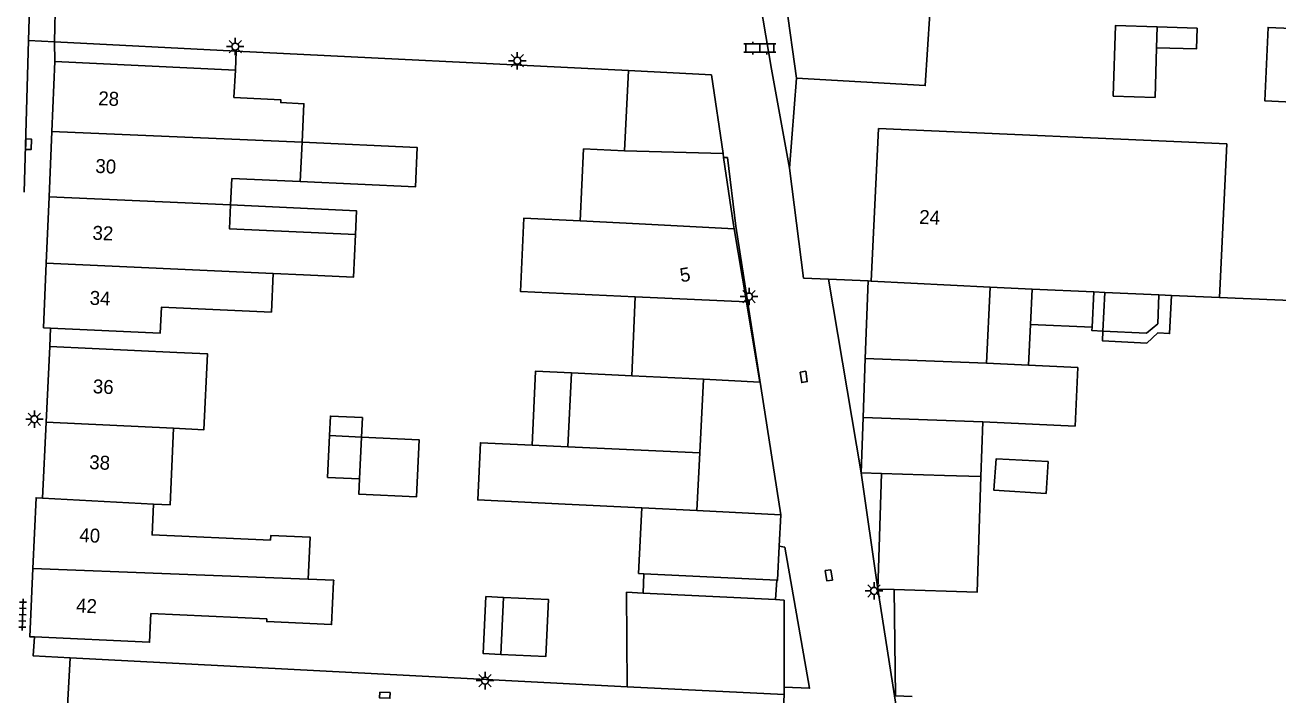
# Model space of a CAD drawing. Extents: x 132998 to 136004, y 396998 to 398512.
# Drawn here: x 133159.2 to 133249, y 397894.1 to 397942.1 of the extents above; entities that cross this region are included whole.
import ezdxf

# ---------------------------------------------------------------- set-up
doc = ezdxf.new("R2010")
doc.units = 0
for name, color, linetype in [('gg-afsc-erfafscheiding', 7, 'Continuous'), ('gg-afsc-hekwerk', 7, 'Continuous'), ('gg-afsc-muur', 7, 'Continuous'), ('gg-anno-huisnummerreeks BGT', 7, 'Continuous'), ('gg-bbg-bijgebouw', 7, 'Continuous'), ('gg-bbg-gedigitaliseerde bebouwing', 7, 'Continuous'), ('gg-bbg-gedigitaliseerde bijgebouw', 7, 'Continuous'), ('gg-bbg-hoofdgebouw', 7, 'Continuous'), ('gg-bbg-luifel en loopbrug', 7, 'Continuous'), ('gg-bbg-tussenscheiding', 7, 'Continuous'), ('gg-knt-verharding', 7, 'Continuous'), ('gt-grn-weggrens', 7, 'Continuous'), ('gt-symb-klinker verharding', 7, 'Continuous'), ('gt-symb-kolk', 7, 'Continuous'), ('gt-symb-kolk center center', 7, 'Continuous'), ('gt-symb-lichtmast', 7, 'Continuous'), ('gt-symb-tegel verharding', 7, 'Continuous')]:
    doc.layers.add(name, color=color, linetype=linetype)

# ---------------------------------------------------------------- blocks, each defined once
blk = doc.blocks.new('gt0-KL1')
at = {"layer": 'gt-symb-klinker verharding'}
for p, q in [((-1.15, 0.3), (1.15, 0.3)), ((-1, -0.3), (-1, 0.3)), ((-0.5, 0.3), (-0.5, 0.45)), ((0, -0.3), (0, 0.3)), ((0.5, 0.3), (0.5, 0.45)), ((1, -0.3), (1, 0.3)), ((-1.15, -0.3), (1.15, -0.3)), ((-0.5, -0.45), (-0.5, -0.3)), ((0.5, -0.45), (0.5, -0.3))]:
    blk.add_line(p, q, dxfattribs=at)
blk = doc.blocks.new('gt0-LMAST')
at = {"layer": 'gt-symb-lichtmast'}
for p, q in [((-0.182, 0.173), (-0.447, 0.438)), ((-0.005, 0.246), (-0.005, 0.621)), ((0.172, 0.173), (0.437, 0.438)), ((-0.255, -0.004), (-0.63, -0.004)), ((-0.182, -0.181), (-0.447, -0.446)), ((-0.005, -0.254), (-0.005, -0.629)), ((0.437, -0.446), (0.172, -0.181)), ((0.245, -0.004), (0.62, -0.004))]:
    blk.add_line(p, q, dxfattribs=at)
blk.add_circle((-0.005, -0.004), 0.25, dxfattribs=at)
blk = doc.blocks.new('gt0-KOLK')
at = {"layer": 'gt-symb-kolk'}
blk.add_lwpolyline([(0, 0), (0.375, 0), (0.375, 0.4), (-0.375, 0.4), (-0.375, 0), (0, 0)], dxfattribs=at)
blk = doc.blocks.new('gt0-KOLKCC')
at = {"layer": 'gt-symb-kolk center center'}
blk.add_lwpolyline([(-0.375, 0.2), (0.375, 0.2), (0.375, -0.2), (-0.375, -0.2)], close=True, dxfattribs=at)
blk = doc.blocks.new('gt0-TEG1')
at = {"layer": 'gt-symb-tegel verharding'}
for p, q in [((-1.125, 0), (1.125, 0)), ((-0.9, -0.25), (-0.9, 0.25)), ((-0.45, -0.25), (-0.45, 0.25)), ((0, -0.25), (0, 0.25)), ((0.45, -0.25), (0.45, 0.25)), ((0.9, -0.25), (0.9, 0.25))]:
    blk.add_line(p, q, dxfattribs=at)

msp = doc.modelspace()

# ---------------------------------------------------------------- linework, layer by layer
at = {"layer": 'gg-afsc-erfafscheiding'}
for p, q in [((133216.799, 397923.882), (133219.63, 397923.76)), ((133213.657, 397904.69), (133213.264, 397904.749)), ((133202.36, 397894.68), (133162.411, 397896.761))]:
    msp.add_line(p, q, dxfattribs=at)
for points in [[(133214.007, 397931.848), (133215.003, 397923.96), (133216.799, 397923.882)], [(133221.51, 397901.643), (133221.596, 397894.022), (133222.795, 397893.973)], [(133162.411, 397896.761), (133159.75, 397896.9), (133159.851, 397898.244)]]:
    msp.add_lwpolyline(points, dxfattribs=at)
at = {"layer": 'gg-afsc-hekwerk'}
msp.add_line((133214.5, 397938.29), (133214.007, 397931.848), dxfattribs=at)
at = {"layer": 'gg-afsc-muur'}
for p, q in [((133174.26, 397938.86), (133174.325, 397940.237)), ((133174.325, 397940.237), (133202.44, 397938.83)), ((133244.82, 397922.57), (133255.245, 397922.154))]:
    msp.add_line(p, q, dxfattribs=at)
at = {"layer": 'gg-bbg-bijgebouw'}
for p, q in [((133214.5, 397938.29), (133213.751, 397943.59)), ((133208.4, 397938.54), (133202.44, 397938.83)), ((133208.4, 397938.54), (133209.228, 397932.893)), ((133209.228, 397932.893), (133209.27, 397932.61)), ((133209.978, 397927.785), (133209.27, 397932.61)), ((133209.978, 397927.785), (133210.026, 397927.499)), ((133219.63, 397923.76), (133219.432, 397918.205)), ((133219.281, 397913.98), (133219.432, 397918.205)), ((133207.564, 397911.429), (133207.833, 397916.715)), ((133219.281, 397913.98), (133219.14, 397910.01)), ((133207.564, 397911.429), (133207.355, 397907.302)), ((133219.14, 397910.01), (133220.6, 397909.96)), ((133220.6, 397909.96), (133220.34, 397901.68)), ((133207.355, 397907.302), (133213.377, 397907.008)), ((133213.377, 397907.008), (133213.264, 397904.749)), ((133220.34, 397901.68), (133221.51, 397901.643)), ((133212.996, 397900.935), (133213.621, 397900.89)), ((133213.621, 397900.89), (133213.611, 397894.64)), ((133202.36, 397894.68), (133213.61, 397894.13)), ((133213.611, 397894.64), (133213.61, 397894.13))]:
    msp.add_line(p, q, dxfattribs=at)
for points in [[(133207.833, 397916.715), (133211.878, 397916.516), (133210.907, 397922.254)], [(133213.264, 397904.749), (133213.142, 397902.314), (133213.081, 397902.318)]]:
    msp.add_lwpolyline(points, dxfattribs=at)
at = {"layer": 'gg-bbg-gedigitaliseerde bebouwing'}
for p, q in [((133220.374, 397934.686), (133245.35, 397933.58)), ((133179.041, 397933.706), (133178.898, 397930.879)), ((133173.91, 397929.205), (133173.998, 397931.108)), ((133173.998, 397931.108), (133177.248, 397930.962)), ((133178.898, 397930.879), (133177.248, 397930.962)), ((133179.146, 397924.194), (133176.965, 397924.304)), ((133231.392, 397923.173), (133228.375, 397923.309)), ((133236.609, 397922.939), (133235.813, 397922.975)), ((133241.387, 397922.724), (133240.492, 397922.764)), ((133244.82, 397922.57), (133241.387, 397922.724)), ((133161.01, 397920.368), (133160.5, 397920.39)), ((133170.063, 397918.641), (133160.95, 397919.06)), ((133179.49, 397902.38), (133181.311, 397902.309))]:
    msp.add_line(p, q, dxfattribs=at)
for points in [[(133182.863, 397927.082), (133173.831, 397927.498), (133173.91, 397929.205)], [(133202.918, 397922.623), (133194.708, 397923.002), (133194.951, 397928.268), (133198.988, 397928.061)], [(133179.146, 397924.194), (133182.722, 397924.029), (133182.863, 397927.082)], [(133161.01, 397920.368), (133168.877, 397920.021), (133168.961, 397921.876), (133176.84, 397921.522), (133176.965, 397924.304)], [(133170.063, 397918.641), (133172.261, 397918.538), (133172.005, 397913.098), (133169.82, 397913.201)], [(133168.381, 397907.765), (133169.575, 397907.712), (133169.82, 397913.201)], [(133176.791, 397905.184), (133168.283, 397905.563), (133168.381, 397907.765)], [(133176.791, 397905.184), (133176.806, 397905.521), (133179.626, 397905.395), (133179.49, 397902.38)]]:
    msp.add_lwpolyline(points, dxfattribs=at)
at = {"layer": 'gg-bbg-gedigitaliseerde bijgebouw'}
for p, q in [((133240.367, 397941.963), (133240.32, 397940.475)), ((133202.164, 397933.083), (133202.44, 397938.83)), ((133228.113, 397917.859), (133228.375, 397923.309)), ((133231.27, 397920.639), (133231.392, 397923.173)), ((133235.691, 397920.44), (133235.813, 397922.975)), ((133236.609, 397922.939), (133236.476, 397920.16)), ((133202.689, 397916.963), (133202.918, 397922.623)), ((133231.27, 397920.639), (133235.691, 397920.44)), ((133231.129, 397917.714), (133228.113, 397917.859)), ((133198.102, 397911.873), (133198.357, 397917.171)), ((133198.357, 397917.171), (133202.689, 397916.963)), ((133227.713, 397909.736), (133227.853, 397913.674)), ((133183.305, 397912.568), (133183.171, 397909.571)), ((133195.538, 397911.993), (133198.102, 397911.873)), ((133203.399, 397907.497), (133197.904, 397907.762)), ((133213.081, 397902.318), (133203.561, 397902.777)), ((133212.996, 397900.935), (133203.494, 397901.393)), ((133193.293, 397896.989), (133193.478, 397901.078))]:
    msp.add_line(p, q, dxfattribs=at)
for points in [[(133213.751, 397943.59), (133224.06, 397942.934), (133223.732, 397937.765), (133214.5, 397938.29)], [(133237.209, 397937.012), (133237.369, 397942.058), (133240.367, 397941.963)], [(133240.32, 397940.475), (133240.207, 397936.917), (133237.209, 397937.012)], [(133202.164, 397933.083), (133199.236, 397933.22), (133198.988, 397928.061)], [(133236.476, 397920.16), (133239.602, 397920.02), (133240.399, 397920.688), (133240.492, 397922.764)], [(133227.853, 397913.674), (133234.47, 397913.356), (133234.671, 397917.544), (133231.129, 397917.714)], [(133183.305, 397912.568), (133183.367, 397913.966), (133181.07, 397914.075), (133181.007, 397912.676)], [(133183.171, 397909.571), (133180.873, 397909.679), (133181.007, 397912.676)], [(133197.904, 397907.762), (133191.639, 397908.064), (133191.836, 397912.167), (133195.538, 397911.993)], [(133232.397, 397908.535), (133228.656, 397908.763), (133228.81, 397911.01), (133232.537, 397910.819), (133232.397, 397908.535)], [(133227.713, 397909.736), (133227.453, 397901.452), (133221.51, 397901.643)], [(133203.561, 397902.777), (133203.17, 397902.796), (133203.399, 397907.497)], [(133203.494, 397901.393), (133202.313, 397901.45), (133202.36, 397894.68)], [(133193.478, 397901.078), (133196.703, 397900.932), (133196.519, 397896.843), (133193.293, 397896.989)]]:
    msp.add_lwpolyline(points, dxfattribs=at)
at = {"layer": 'gg-bbg-hoofdgebouw'}
for p, q in [((133161.32, 397939.48), (133161.105, 397934.476)), ((133174.26, 397938.86), (133161.32, 397939.48)), ((133220.374, 397934.686), (133219.856, 397923.748)), ((133161.105, 397934.476), (133160.903, 397929.777)), ((133244.82, 397922.57), (133245.35, 397933.58)), ((133160.903, 397929.777), (133160.7, 397925.035)), ((133210.026, 397927.499), (133210.907, 397922.254)), ((133160.7, 397925.035), (133160.5, 397920.39)), ((133219.856, 397923.748), (133219.63, 397923.76)), ((133160.95, 397919.06), (133160.695, 397913.63)), ((133160.695, 397913.63), (133160.44, 397908.2)), ((133181.305, 397902.187), (133181.311, 397902.309))]:
    msp.add_line(p, q, dxfattribs=at)
for points in [[(133174.26, 397938.86), (133174.16, 397936.91), (133177.52, 397936.74), (133177.51, 397936.54), (133179.17, 397936.46), (133179.041, 397933.706)], [(133160.44, 397908.2), (133159.97, 397908.22), (133159.741, 397903.15)], [(133159.741, 397903.15), (133159.52, 397898.26), (133159.851, 397898.244)], [(133159.851, 397898.244), (133168.111, 397897.872), (133168.204, 397899.92), (133176.515, 397899.543), (133176.506, 397899.353), (133181.161, 397899.133), (133181.305, 397902.187)]]:
    msp.add_lwpolyline(points, dxfattribs=at)
at = {"layer": 'gg-bbg-luifel en loopbrug'}
for p, q in [((133231.129, 397917.714), (133231.27, 397920.639)), ((133203.494, 397901.393), (133203.561, 397902.777)), ((133212.996, 397900.935), (133213.081, 397902.318))]:
    msp.add_line(p, q, dxfattribs=at)
for points in [[(133240.32, 397940.475), (133243.176, 397940.384), (133243.223, 397941.873), (133240.367, 397941.963)], [(133251.108, 397941.802), (133248.321, 397941.932), (133248.075, 397936.668), (133252.499, 397936.458)], [(133178.898, 397930.879), (133187.17, 397930.492), (133187.302, 397933.32), (133179.041, 397933.706)], [(133182.863, 397927.082), (133182.942, 397928.789), (133173.91, 397929.205)], [(133236.476, 397920.16), (133236.443, 397919.461), (133239.628, 397919.31), (133240.409, 397920.03), (133241.257, 397919.992), (133241.387, 397922.724)], [(133236.476, 397920.16), (133235.679, 397920.198), (133235.691, 397920.44)], [(133198.357, 397917.171), (133195.793, 397917.294), (133195.538, 397911.993)], [(133183.171, 397909.571), (133183.122, 397908.475), (133187.249, 397908.29), (133187.432, 397912.383), (133183.305, 397912.568)], [(133193.478, 397901.078), (133192.232, 397901.138), (133192.035, 397897.049), (133193.293, 397896.989)]]:
    msp.add_lwpolyline(points, dxfattribs=at)
at = {"layer": 'gg-bbg-tussenscheiding'}
for p, q in [((133177.374, 397933.778), (133161.105, 397934.476)), ((133177.374, 397933.778), (133179.041, 397933.706)), ((133202.164, 397933.083), (133209.228, 397932.893)), ((133160.903, 397929.777), (133173.91, 397929.205)), ((133203.214, 397927.846), (133198.988, 397928.061)), ((133210.026, 397927.499), (133203.214, 397927.846)), ((133160.7, 397925.035), (133176.965, 397924.304)), ((133219.856, 397923.748), (133228.375, 397923.309)), ((133235.813, 397922.975), (133231.392, 397923.173)), ((133240.492, 397922.764), (133236.609, 397922.939)), ((133210.907, 397922.254), (133202.918, 397922.623)), ((133228.113, 397917.859), (133219.432, 397918.205)), ((133202.689, 397916.963), (133207.833, 397916.715)), ((133227.853, 397913.674), (133219.281, 397913.98)), ((133169.82, 397913.201), (133160.695, 397913.63)), ((133183.305, 397912.568), (133181.007, 397912.676)), ((133198.102, 397911.873), (133207.564, 397911.429)), ((133220.6, 397909.96), (133225.104, 397909.818)), ((133225.104, 397909.818), (133227.713, 397909.736)), ((133168.381, 397907.765), (133160.44, 397908.2)), ((133203.399, 397907.497), (133207.355, 397907.302)), ((133159.741, 397903.15), (133179.49, 397902.38))]:
    msp.add_line(p, q, dxfattribs=at)
at = {"layer": 'gg-knt-verharding'}
for p, q in [((133159.574, 397946.045), (133159.431, 397940.983)), ((133161.28, 397940.89), (133161.41, 397945.95)), ((133159.431, 397940.983), (133159.126, 397930.112)), ((133174.325, 397940.237), (133161.28, 397940.89)), ((133161.01, 397920.368), (133160.95, 397919.06)), ((133220.34, 397901.68), (133222.495, 397887.86)), ((133213.461, 397891.066), (133213.61, 397894.13))]:
    msp.add_line(p, q, dxfattribs=at)
msp.add_lwpolyline([(133213.377, 397907.008), (133210.16, 397927.69), (133209.54, 397932.6), (133209.27, 397932.61)], dxfattribs=at)
at = {"layer": 'gt-grn-weggrens'}
for p, q in [((133159.431, 397940.983), (133161.28, 397940.89)), ((133161.28, 397940.89), (133161.32, 397939.48)), ((133216.799, 397923.882), (133219.14, 397910.01)), ((133219.14, 397910.01), (133220.34, 397901.68)), ((133162.411, 397896.761), (133162.23, 397893.29))]:
    msp.add_line(p, q, dxfattribs=at)
for points in [[(133211.896, 397943.708), (133212.71, 397938.94), (133214.007, 397931.848)], [(133213.611, 397894.64), (133215.44, 397894.57), (133213.657, 397904.69)]]:
    msp.add_lwpolyline(points, dxfattribs=at)

# ---------------------------------------------------------------- block references
at = {"layer": 'gt-symb-klinker verharding'}
msp.add_blockref('gt0-KL1', (133211.877, 397940.444), dxfattribs=at)
at = {"layer": 'gt-symb-kolk', "rotation": -91.60386277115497}
msp.add_blockref('gt0-KOLK', (133159.223, 397933.561), dxfattribs=at)
at = {"layer": 'gt-symb-kolk center center'}
for p, rotation in [((133215.019, 397916.882), -81.02737338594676), ((133216.818, 397902.664), -81.027373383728), ((133184.973, 397894.075), -2.693611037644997)]:
    msp.add_blockref('gt0-KOLKCC', p, dxfattribs=dict(at, rotation=rotation))
at = {"layer": 'gt-symb-lichtmast'}
for p in [(133174.254, 397940.557), (133194.484, 397939.541), (133211.1, 397922.647), (133159.857, 397913.856), (133220.064, 397901.553), (133192.169, 397895.119)]:
    msp.add_blockref('gt0-LMAST', p, dxfattribs=at)
at = {"layer": 'gt-symb-tegel verharding', "rotation": 88.39613722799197}
msp.add_blockref('gt0-TEG1', (133159.006, 397899.842), dxfattribs=at)

# ---------------------------------------------------------------- texts
at = {"layer": 'gg-anno-huisnummerreeks BGT'}
for s, rotation, p in [('28', 357.5, (133164.412, 397936.359)), ('30', 357.5, (133164.203, 397931.507)), ('24', 357.3, (133223.278, 397927.856)), ('32', 357.5, (133163.998, 397926.718)), ('5', 9.5, (133206.222, 397923.657)), ('34', 357.5, (133163.798, 397922.056)), ('36', 357.3, (133164.02, 397915.714)), ('38', 357.3, (133163.765, 397910.284)), ('40', 357.4, (133163.054, 397905.058)), ('42', 357.4, (133162.826, 397900.009))]:
    msp.add_text(s, height=1, rotation=rotation, dxfattribs=at).set_placement(p)

doc.saveas('drawing.dxf')
